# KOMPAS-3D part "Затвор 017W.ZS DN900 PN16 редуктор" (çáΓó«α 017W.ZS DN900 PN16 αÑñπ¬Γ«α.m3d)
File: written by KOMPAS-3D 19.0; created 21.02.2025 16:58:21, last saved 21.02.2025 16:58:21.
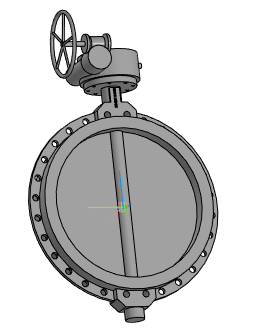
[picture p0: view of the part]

Document properties: Автор: Евгений; Полное имя файла: Затвор 017W.ZS DN900 PN16 редуктор.a3d

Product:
- Part/product: Затвор 017W.ZS DN900 PN16 редуктор
    Масса: 713.757

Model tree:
1. Операция без истории:1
